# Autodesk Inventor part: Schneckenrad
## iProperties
Created: 2008-11
Part Number: Schneckenrad
Material: Steel, Mild
Document SubType Name: Modeling
Designer: nkrapf
Density: 7.86 g/cm^3
CustomPartVersion: 1
Author: nkrapf
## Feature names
1. Grundkörper [Revolution]
2. Zahn [Revolution]
3. Zahnanordnung [Circular Pattern]
